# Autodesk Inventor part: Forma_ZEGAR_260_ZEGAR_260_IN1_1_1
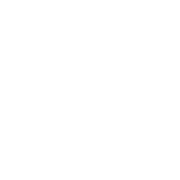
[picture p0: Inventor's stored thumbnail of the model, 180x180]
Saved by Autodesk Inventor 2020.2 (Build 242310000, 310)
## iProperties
Created: 2015-01
Part Number: Forma_ZEGAR_260_ZEGAR_260_IN1_1_1
Material: Ogólny
Document SubType Name: Modeling
Designer: F.Stasiak
Density: 1 g/cm^3
Appearance: Domyślna
Catalog Web Link: www.expertbooks.pl
Manager: www.cadconsulting.pl
Company: Fabian Stasiak CAD Consulting
Author: F.Stasiak
Subject: Zbiór ćwiczeń. Autodesk Inventor 2020. Kurs Professional
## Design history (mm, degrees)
node "Forma_ZEGAR_260_ZEGAR_260_IN1_Base"
feature "Bryła1::Forma_ZEGAR_260_ZEGAR_260_IN1_Base"
tag "Bryła wyprowadzona1"
node "Bryła1"
feature "Forma_ZEGAR_260_ZEGAR_260_IN1_Base_Bodies"
